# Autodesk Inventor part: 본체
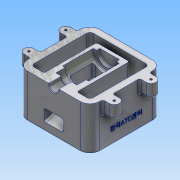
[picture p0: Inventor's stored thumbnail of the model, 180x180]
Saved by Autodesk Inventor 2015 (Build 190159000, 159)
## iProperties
Created: 2018-01
Part Number: 본체
Material: 알루미늄 6061
Document SubType Name: Modeling
Designer: SCD-A18
Density: 2.7 g/cm^3
Appearance: 알루미늄 - 평지
Mass: 996.176 g
Surface Area: 833.532 cm^2
Volume: 368.954 cm^3
Author: SCD-A18
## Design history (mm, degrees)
sketch "스케치2"
  geometry: L1 (55, -55)-(-55, -55); L2 (-55, -55)-(-55, 55); L3 (-55, 55)-(55, 55); L4 (55, 55)-(55, -55); L5 (55, -55)-(-55, 55); L6 (-55, -55)-(55, 55); 1 further point
  constraints: 12 end point, 2 midpoint, 2 parallel, 1 horizontal, 1 perpendicular
  dimensions: "d4" = 110 distance of L2.end L3.end; "d5" = 110 distance of L1.end L2.end
extrude "돌출2" new body sketch "스케치2" distance "d6" = 65; taper "d7" = 0 deg
sketch "스케치3"
  geometry: L1 (-55, 55)-(55, 55) reference; L2 (-55, -55)-(-55, 55) reference; L3 (55, -55)-(-55, -55) reference; L4 (55, 55)-(55, -55) reference; L5 (-45, 25)-(35, 25); L6 (35, 25)-(35, -25); L7 (35, -25)-(-45, -25); L8 (-45, 25)-(-45, 45); L9 (-45, 45)-(45, 45); L10 (45, 45)-(45, -45); L11 (45, -45)-(-45, -45); L12 (-45, -45)-(-45, -25); 1 further point
  constraints: 16 end point, 6 perpendicular, 1 horizontal, 1 point on line, 1 vertical
  dimensions: "d9" = 10 distance between parallel lines of L1 L9; "d10" = 10 distance between parallel lines of L2 L8; "d11" = 30 distance between parallel lines of L1 L5; "d12" = 10 distance between parallel lines of L4 L10; "d13" = 20 distance between parallel lines of L4 L6; "d14" = 10 distance between parallel lines of L3 L11; "d15" = 50 distance between parallel lines of L7 L5
extrude "돌출3" cut sketch "스케치3" stored distance "d16" = 65; taper "d17" = 0 deg
sketch "스케치4"
  geometry: L1 (35, -25)-(35, 25) reference; L2 (-55, -55)-(-55, 55) reference; L3 (-55, 0)-(35, 0); L4 (-55, 7.5)-(-36, 7.5); L5 (-36, 7.5)-(-36, 16); L6 (-36, 16)-(-22, 16); L7 (-22, 16)-(-22, 20); L8 (-22, 20)-(25, 20); L9 (25, 20)-(25, 15); L10 (25, 15)-(30, 15); L11 (30, 15)-(30, 0); L12 (-55, 7.5)-(-55, 0); 1 further point
  constraints: 20 end point, 8 perpendicular, 2 midpoint, 2 point on line, 1 collinear
  dimensions: "d18" = 15 diameter of L4 L3; "d19" = 32 diameter of L6 L3; "d20" = 40 diameter of L8 L3; "d21" = 30 diameter of L10 L3; "d22" = 19 distance from line of L5 L4.start; "d23" = 14 distance of L5.end L6.end; "d24" = 47 distance of L7.end L8.end; "d25" = 5 distance of L9.end L10.end
revolve "회전1" sketch "스케치4" stored, may be unused: angle "d26" = 180 deg
sketch "스케치5"
  geometry: L1 (17, -15)-(-20, -15); L2 (-20, -15)-(-20, 15); L3 (-20, 15)-(17, 15); L4 (17, 15)-(17, -15); L5 (17, -15)-(-20, 15); L6 (-20, -15)-(17, 15); L7 (-25, -15)-(-25, 15) reference
  constraints: 12 end point, 2 parallel, 1 horizontal, 1 perpendicular
  dimensions: "d27" = 37 distance of L2.end L3.end; "d28" = 30 distance of L1.end L2.end; "d84" = 5 distance between parallel lines of L7 L2
extrude "돌출4" cut sketch "스케치5" distance "d29" = 20; taper "d30" = 0 deg
sketch "스케치6"
  geometry: L1 (35, 0)-(35, -65) reference; L2 (35, -35)-(-45, -56.436); L3 (-45, -56.436)-(-45, -65); L4 (-45, -65)-(35, -65) reference; L5 (-55, 0)-(-55, -65) reference; L6 (-55, -35.939)-(-17, -25.757); L7 (-17, -25.757)-(-17, -20); L8 (20, -33.843)-(20, -20); L9 (20, -13.229)-(20, -20) reference; L10 (20, -33.843)-(-55, -53.939); L11 (-55, -35.939)-(-55, -53.939); L12 (-17, -20)-(20, -20); L13 (-17, -20)-(20, -20) reference; L14 (-45, -65)-(35, -65); L15 (35, -35)-(35, -65); 1 further point
  constraints: 20 end point, 4 point on line, 3 collinear, 3 vertical, 1 horizontal
  dimensions: "d31" = 30 distance of L1.end L2.start; "d32" = 105 deg angle of L3 L2; "d33" = 75 deg angle of L5 L6; "d36" = 5 distance between parallel lines of L2 L10; "d37" = 10 distance of L5.end L3.end; "d38" = 18 distance of L10.end L6.start
extrude "돌출5" cut sketch "스케치6" stored distance "d41" = 30; taper "d42" = 0 deg
extrude "돌출6" cut sketch "스케치6" stored distance "d43" = 50; taper "d44" = 0 deg
fillet "모깎기1" dims "d45" = 1
chamfer "모따기1" distance "d46" = 1; stored, may be unused: second distance "d47" = 2, angle "d48" = 45 deg
fillet "모깎기3" dims "d50" = 3
fillet "모깎기5" dims "d52" = 3
fillet "모깎기6" dims "d53" = 3
fillet "모깎기7" dims "d54" = 3
sketch "스케치7"
  geometry: L1 (-55, 55)-(55, 55) reference; L2 (-55, 8.5)-(-55, 55) reference; L3 (-55, 55)-(55, 55) reference; L4 (-35.5, 55)-(-35.5, 65); L5 (-20.5, 65)-(-20.5, 55); L6 (-35.5, 55)-(-20.5, 55); A1 r 7.5 centre (-28, 65) between (-20.5, 65) and (-35.5, 65); 1 further point
  constraints: 6 end point, 2 point on circle, 2 point on line, 2 tangent, 1 centre point, 1 collinear, 1 perpendicular, 1 vertical
  dimensions: "d55" = 10 distance from line of A1.centre L3; "d56" = 7.5 radius of A1; "d58" = 27 distance from line of A1.centre L2
extrude "돌출7" join sketch "스케치7" distance "d59" = 20; taper "d60" = 0 deg
hole "구멍1" diameter "d63" = 3.242; stored, may be unused: countersink angle "d67" = 90 deg, drill point angle "d69" = 118 deg; dims "d61" = 10, "d62" = 10, "d64" = 9, "d65" = 4, "d66" = 2, "d68" = 11
fillet "모깎기8" dims "d73" = 3
fillet "모깎기9" dims "d74" = 15
fillet "모깎기10" dims "d75" = 5
fillet "모깎기11" dims "d76" = 3
fillet "모깎기12" dims "d77" = 3
fillet "모깎기13" dims "d78" = 3
fillet "모깎기14" dims "d79" = 3
sketch "스케치9" dims "d12" = 10, "d13" = 20
  geometry: L1 (95, 0)-(80, 0) reference; L2 (-15, 65)-(-15, 0) reference; 2 further points
  constraints: 1 other
  dimensions: "d80" = 20 distance from line of L1 point (40, 20); "d81" = 55 distance from line of L2 point (40, 20)
feature "엠보싱1" sketch "스케치9" dims "d4" = 110, "d5" = 110, "d9" = 10, "d10" = 10, "d11" = 30, "d12" = 10, "d13" = 20, "d14" = 10, "d15" = 50, "d82" = 0.5, "d83" = 0
node "솔리드2"
pattern_linear "직사각형 패턴1" dims "d72" = 56
mirror "대칭1"
